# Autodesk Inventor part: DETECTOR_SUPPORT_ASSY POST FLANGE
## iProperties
Shininess: 64.0
Length Units: 11272
Angle Units: 11279
Time Units: 11290
Mass Units: 11286
Length Display Precision: 3
Angle Display Precision: 2
Compacted: True
Part Number: DETECTOR_SUPPORT_ASSY POST FLANGE
Document SubType Name: Modeling
Created: 2004-08
Designer: John Blackburn
Material: BRASS, SOFT YELLOW BRASS
Manufacturer: Standard
Standards Organization: Custom
Density: 0.0
Volumn: 0.0
Area: 0.0
PropertySet Name: Model Information
Control State: 0
Master: False
Checked Out: False
Author: John Blackburn
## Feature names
1. ExtrusionBlind1
2. Hole1
